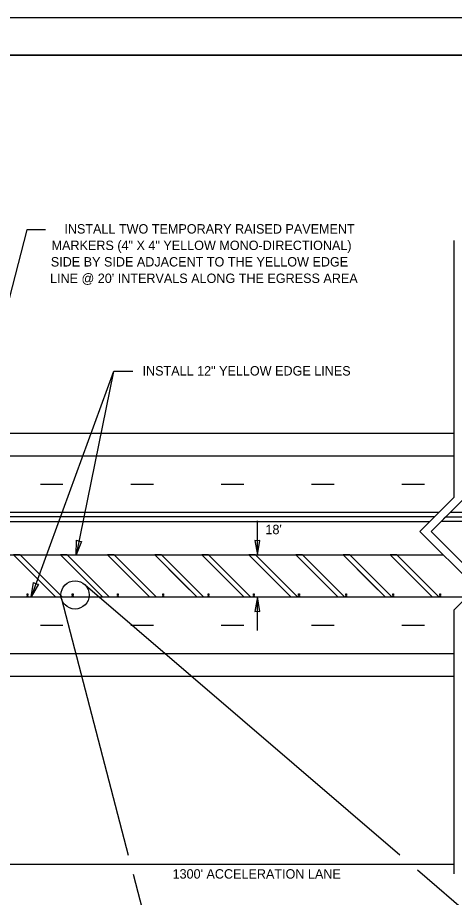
# Model space of a CAD drawing. Extents: x -2433 to -1135, y -5611 to -4633.
# Drawn here: x -1989.1 to -1803.5, y -5006.7 to -4632.8 of the extents above; entities that cross this region are included whole.
import ezdxf

# ---------------------------------------------------------------- set-up
doc = ezdxf.new("R2010")
doc.units = 0
for name, color, linetype in [('Level 42', 7, 'Continuous'), ('Level 45', 7, 'Continuous'), ('Level 46', 7, 'Continuous'), ('Level 48', 7, 'Continuous'), ('Level 49', 7, 'Continuous'), ('Level 50', 7, 'Continuous'), ('TR_WZ_TC_Edge Lines', 7, 'Continuous')]:
    doc.layers.add(name, color=color, linetype=linetype)

msp = doc.modelspace()

# ---------------------------------------------------------------- linework, layer by layer
at = {"layer": 'Level 42'}
msp.add_line((-1170.57, -4648.81), (-2364.77, -4648.78), dxfattribs=at)
msp.add_lwpolyline([(-2364.77, -4648.78), (-1304.73, -4648.78), (-1304.73, -5430.02), (-2364.77, -5430.02)], close=True, dxfattribs=at)
at = {"layer": 'Level 45'}
for p, q in [((-2323.46, -4843.04), (-1810.06, -4843.04)), ((-1805.25, -4843.04), (-1332.46, -4843.04)), ((-2323.46, -4879.04), (-1798.16, -4879.04)), ((-1985.09, -4878.08), (-1985.09, -4877.76)), ((-1985.09, -4877.76), (-1984.77, -4877.76)), ((-1984.77, -4878.08), (-1985.09, -4878.08)), ((-1985.09, -4878.72), (-1985.09, -4878.4)), ((-1985.09, -4878.4), (-1984.77, -4878.4)), ((-1984.77, -4878.72), (-1985.09, -4878.72)), ((-1984.77, -4877.76), (-1984.77, -4878.08)), ((-1984.77, -4878.4), (-1984.77, -4878.72)), ((-1965.86, -4878.08), (-1965.86, -4877.76)), ((-1965.86, -4877.76), (-1965.54, -4877.76)), ((-1965.54, -4878.08), (-1965.86, -4878.08)), ((-1965.86, -4878.72), (-1965.86, -4878.4)), ((-1965.86, -4878.4), (-1965.54, -4878.4)), ((-1965.54, -4878.72), (-1965.86, -4878.72)), ((-1965.54, -4877.76), (-1965.54, -4878.08)), ((-1965.54, -4878.4), (-1965.54, -4878.72)), ((-1946.63, -4878.08), (-1946.63, -4877.76)), ((-1946.63, -4877.76), (-1946.31, -4877.76)), ((-1946.31, -4878.08), (-1946.63, -4878.08)), ((-1946.63, -4878.72), (-1946.63, -4878.4)), ((-1946.63, -4878.4), (-1946.31, -4878.4)), ((-1946.31, -4878.72), (-1946.63, -4878.72)), ((-1946.31, -4877.76), (-1946.31, -4878.08)), ((-1946.31, -4878.4), (-1946.31, -4878.72)), ((-1927.4, -4878.08), (-1927.4, -4877.76)), ((-1927.4, -4877.76), (-1927.08, -4877.76)), ((-1927.08, -4878.08), (-1927.4, -4878.08)), ((-1927.4, -4878.72), (-1927.4, -4878.4)), ((-1927.4, -4878.4), (-1927.08, -4878.4)), ((-1927.08, -4878.72), (-1927.4, -4878.72)), ((-1927.08, -4877.76), (-1927.08, -4878.08)), ((-1927.08, -4878.4), (-1927.08, -4878.72)), ((-1908.17, -4878.08), (-1908.17, -4877.76)), ((-1908.17, -4877.76), (-1907.85, -4877.76)), ((-1907.85, -4878.08), (-1908.17, -4878.08)), ((-1908.17, -4878.72), (-1908.17, -4878.4)), ((-1908.17, -4878.4), (-1907.85, -4878.4)), ((-1907.85, -4878.72), (-1908.17, -4878.72)), ((-1907.85, -4877.76), (-1907.85, -4878.08)), ((-1907.85, -4878.4), (-1907.85, -4878.72)), ((-1888.94, -4878.08), (-1888.94, -4877.76)), ((-1888.94, -4877.76), (-1888.62, -4877.76)), ((-1888.62, -4878.08), (-1888.94, -4878.08)), ((-1888.94, -4878.72), (-1888.94, -4878.4)), ((-1888.94, -4878.4), (-1888.62, -4878.4)), ((-1888.62, -4878.72), (-1888.94, -4878.72)), ((-1888.62, -4877.76), (-1888.62, -4878.08)), ((-1888.62, -4878.4), (-1888.62, -4878.72)), ((-1869.71, -4878.08), (-1869.71, -4877.76)), ((-1869.71, -4877.76), (-1869.39, -4877.76)), ((-1869.39, -4878.08), (-1869.71, -4878.08)), ((-1869.71, -4878.72), (-1869.71, -4878.4)), ((-1869.71, -4878.4), (-1869.39, -4878.4)), ((-1869.39, -4878.72), (-1869.71, -4878.72)), ((-1869.39, -4877.76), (-1869.39, -4878.08)), ((-1869.39, -4878.4), (-1869.39, -4878.72)), ((-1849.71, -4878.08), (-1849.71, -4877.76)), ((-1849.71, -4877.76), (-1849.39, -4877.76)), ((-1849.39, -4878.08), (-1849.71, -4878.08)), ((-1849.71, -4878.72), (-1849.71, -4878.4)), ((-1849.71, -4878.4), (-1849.39, -4878.4)), ((-1849.39, -4878.72), (-1849.71, -4878.72)), ((-1849.39, -4877.76), (-1849.39, -4878.08)), ((-1849.39, -4878.4), (-1849.39, -4878.72)), ((-1829.71, -4878.08), (-1829.71, -4877.76)), ((-1829.71, -4877.76), (-1829.39, -4877.76)), ((-1829.39, -4878.08), (-1829.71, -4878.08)), ((-1829.71, -4878.72), (-1829.71, -4878.4)), ((-1829.71, -4878.4), (-1829.39, -4878.4)), ((-1829.39, -4878.72), (-1829.71, -4878.72)), ((-1829.39, -4877.76), (-1829.39, -4878.08)), ((-1829.39, -4878.4), (-1829.39, -4878.72)), ((-1809.71, -4878.08), (-1809.71, -4877.76)), ((-1809.71, -4877.76), (-1809.39, -4877.76)), ((-1809.39, -4878.08), (-1809.71, -4878.08)), ((-1809.71, -4878.72), (-1809.71, -4878.4)), ((-1809.71, -4878.4), (-1809.39, -4878.4)), ((-1809.39, -4878.72), (-1809.71, -4878.72)), ((-1809.39, -4877.76), (-1809.39, -4878.08)), ((-1809.39, -4878.4), (-1809.39, -4878.72))]:
    msp.add_line(p, q, dxfattribs=at)
at = {"layer": 'Level 46'}
for p, q in [((-1985.23, -4722.95), (-2024.85, -4877.06)), ((-1977.23, -4722.95), (-1985.23, -4722.95)), ((-1948.33, -4783.18), (-1983.39, -4879.04)), ((-1948.33, -4783.18), (-1964.18, -4861.2)), ((-1940.18, -4783.18), (-1948.18, -4783.18)), ((-2323.46, -4809.44), (-1803.64, -4809.44)), ((-2323.46, -4819.04), (-1803.64, -4819.04)), ((-1979.41, -4831.04), (-1969.81, -4831.04)), ((-1941.01, -4831.04), (-1931.41, -4831.04)), ((-1902.61, -4831.04), (-1893.01, -4831.04)), ((-1864.21, -4831.04), (-1854.61, -4831.04)), ((-1825.81, -4831.04), (-1816.21, -4831.04)), ((-1887.25, -4861.2), (-1887.25, -4846.73)), ((-1960.46, -4873.92), (-1826.68, -4988.63)), ((-1887.25, -4893.35), (-1887.25, -4879.04)), ((-1970.45, -4879.87), (-1942.11, -4988.76)), ((-1979.41, -4891.04), (-1969.81, -4891.04)), ((-1941.01, -4891.04), (-1931.41, -4891.04)), ((-1902.61, -4891.04), (-1893.01, -4891.04)), ((-1864.21, -4891.04), (-1854.61, -4891.04)), ((-1825.81, -4891.04), (-1816.21, -4891.04)), ((-2323.46, -4903.04), (-1803.64, -4903.04)), ((-2323.46, -4912.64), (-1803.64, -4912.64)), ((-2149.01, -4992.52), (-1803.64, -4992.52)), ((-1819.2, -4995.04), (-1752.76, -5052.02)), ((-1940.02, -4996.81), (-1905.06, -5131.15))]:
    msp.add_line(p, q, dxfattribs=at)
msp.add_circle((-1964.7, -4878.16), 6, dxfattribs=at)
at = {"layer": 'Level 48'}
for p, q in [((-1812.06, -4845.04), (-2323.46, -4845.04)), ((-1813.98, -4846.96), (-1812.06, -4845.04)), ((-1809.17, -4846.96), (-1807.25, -4845.04)), ((-1807.25, -4845.04), (-1493.44, -4845.04)), ((-2323.46, -4846.96), (-1813.98, -4846.96)), ((-1494.3, -4846.96), (-1809.17, -4846.96))]:
    msp.add_line(p, q, dxfattribs=at)
at = {"layer": 'Level 49'}
for p, q in [((-1964.18, -4861.2), (-1964.02, -4854.96)), ((-1961.89, -4855.4), (-1964.18, -4861.2)), ((-1964.02, -4854.96), (-1962.99, -4855.37)), ((-1962.99, -4855.37), (-1961.89, -4855.4)), ((-1887.25, -4855.24), (-1888.33, -4855.05)), ((-1888.33, -4855.05), (-1887.25, -4861.2)), ((-1887.25, -4861.2), (-1886.16, -4855.05)), ((-1886.16, -4855.05), (-1887.25, -4855.24)), ((-1983.39, -4879.04), (-1982.3, -4872.9)), ((-1980.26, -4873.64), (-1983.39, -4879.04)), ((-1982.3, -4872.9), (-1981.35, -4873.45)), ((-1981.35, -4873.45), (-1980.26, -4873.64)), ((-1887.25, -4879.04), (-1888.33, -4885.19)), ((-1886.16, -4885.19), (-1887.25, -4879.04)), ((-1888.33, -4885.19), (-1887.25, -4885)), ((-1887.25, -4885), (-1886.16, -4885.19))]:
    msp.add_line(p, q, dxfattribs=at)
at = {"layer": 'Level 50'}
for p, q in [((-1803.64, -4836.63), (-1803.64, -4727.54)), ((-1818.23, -4851.21), (-1803.64, -4836.63)), ((-1813.42, -4851.21), (-1800.24, -4838.04)), ((-1794.28, -4875.16), (-1818.23, -4851.21)), ((-1789.47, -4875.16), (-1813.42, -4851.21)), ((-1803.64, -4884.52), (-1794.28, -4875.16)), ((-1803.64, -4996.72), (-1803.64, -4884.52))]:
    msp.add_line(p, q, dxfattribs=at)
msp.add_lwpolyline([(-2432.94, -4632.82), (-1157.59, -4632.82), (-1157.59, -5447.91), (-2432.94, -5447.91)], close=True, dxfattribs=at)
at = {"layer": 'TR_WZ_TC_Edge Lines'}
for p, q in [((-2149.01, -4861.2), (-1808.24, -4861.2)), ((-1973, -4879.04), (-1990.84, -4861.2)), ((-1988.01, -4861.2), (-1990.84, -4861.2)), ((-1970.17, -4879.04), (-1988.01, -4861.2)), ((-1970.17, -4879.04), (-1988.01, -4861.2)), ((-1953, -4879.04), (-1970.84, -4861.2)), ((-1968.01, -4861.2), (-1970.84, -4861.2)), ((-1950.17, -4879.04), (-1968.01, -4861.2)), ((-1950.17, -4879.04), (-1968.01, -4861.2)), ((-1933, -4879.04), (-1950.84, -4861.2)), ((-1948.01, -4861.2), (-1950.84, -4861.2)), ((-1930.17, -4879.04), (-1948.01, -4861.2)), ((-1930.17, -4879.04), (-1948.01, -4861.2)), ((-1913, -4879.04), (-1930.84, -4861.2)), ((-1928.01, -4861.2), (-1930.84, -4861.2)), ((-1910.17, -4879.04), (-1928.01, -4861.2)), ((-1910.17, -4879.04), (-1928.01, -4861.2)), ((-1893, -4879.04), (-1910.84, -4861.2)), ((-1908.01, -4861.2), (-1910.84, -4861.2)), ((-1890.17, -4879.04), (-1908.01, -4861.2)), ((-1890.17, -4879.04), (-1908.01, -4861.2)), ((-1873, -4879.04), (-1890.84, -4861.2)), ((-1888.01, -4861.2), (-1890.84, -4861.2)), ((-1870.17, -4879.04), (-1888.01, -4861.2)), ((-1870.17, -4879.04), (-1888.01, -4861.2)), ((-1853, -4879.04), (-1870.84, -4861.2)), ((-1868.01, -4861.2), (-1870.84, -4861.2)), ((-1850.17, -4879.04), (-1868.01, -4861.2)), ((-1850.17, -4879.04), (-1868.01, -4861.2)), ((-1833, -4879.04), (-1850.84, -4861.2)), ((-1848.01, -4861.2), (-1850.84, -4861.2)), ((-1830.17, -4879.04), (-1848.01, -4861.2)), ((-1830.17, -4879.04), (-1848.01, -4861.2)), ((-1813, -4879.04), (-1830.84, -4861.2)), ((-1828.01, -4861.2), (-1830.84, -4861.2)), ((-1810.17, -4879.04), (-1828.01, -4861.2)), ((-1810.17, -4879.04), (-1828.01, -4861.2)), ((-1973, -4879.04), (-1970.17, -4879.04)), ((-1953, -4879.04), (-1950.17, -4879.04)), ((-1933, -4879.04), (-1930.17, -4879.04)), ((-1913, -4879.04), (-1910.17, -4879.04)), ((-1893, -4879.04), (-1890.17, -4879.04)), ((-1873, -4879.04), (-1870.17, -4879.04)), ((-1853, -4879.04), (-1850.17, -4879.04)), ((-1833, -4879.04), (-1830.17, -4879.04)), ((-1813, -4879.04), (-1810.17, -4879.04))]:
    msp.add_line(p, q, dxfattribs=at)
for points in [[(-1990.84, -4861.2), (-1978.84, -4873.2), (-1973, -4879.04)], [(-1970.84, -4861.2), (-1958.84, -4873.2), (-1953, -4879.04)], [(-1950.84, -4861.2), (-1938.84, -4873.2), (-1933, -4879.04)], [(-1930.84, -4861.2), (-1918.84, -4873.2), (-1913, -4879.04)], [(-1910.84, -4861.2), (-1898.84, -4873.2), (-1893, -4879.04)], [(-1890.84, -4861.2), (-1878.84, -4873.2), (-1873, -4879.04)], [(-1870.84, -4861.2), (-1858.84, -4873.2), (-1853, -4879.04)], [(-1850.84, -4861.2), (-1838.84, -4873.2), (-1833, -4879.04)], [(-1830.84, -4861.2), (-1818.84, -4873.2), (-1813, -4879.04)]]:
    msp.add_lwpolyline(points, dxfattribs=at)

# ---------------------------------------------------------------- texts
at = {"layer": 'Level 42'}
for s, p in [('INSTALL TWO TEMPORARY RAISED PAVEMENT', (-1969.23, -4724.6)), ('MARKERS (4" X 4" YELLOW MONO-DIRECTIONAL)', (-1974.66, -4731.6)), ('SIDE BY SIDE ADJACENT TO THE YELLOW EDGE', (-1974.99, -4738.6)), ("LINE @ 20' INTERVALS ALONG THE EGRESS AREA", (-1975.32, -4745.6)), ('INSTALL 12" YELLOW EDGE LINES', (-1936.02, -4784.93)), ("18'", (-1883.81, -4852.35)), ("1300' ACCELERATION LANE", (-1923.26, -4998.73))]:
    msp.add_text(s, height=4, dxfattribs=at).set_placement(p)

doc.saveas('drawing.dxf')
